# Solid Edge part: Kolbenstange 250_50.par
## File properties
Username: ahadarics
Dokumentum tartalom típus: 0
Author: ahadarics
Last saved by: ahadarics
Revision: 80
Sűrűség: 0,000 kg/m^3
Pontosság: 0,990
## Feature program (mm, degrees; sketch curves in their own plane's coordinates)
base feature "unnamed BaseFeature 1"
thread "unnamed Thread 1"
chamfer "Letörés_1"  SetBackValue2 = 20 deg
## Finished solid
Body 1: solid body, 19 faces, 27 edges, 11 vertices.
  Faces by surface: plane 8, cylinder 5, cone 3, torus 3
  Edges by curve: circle 15, line 7, curve on surface 3, ellipse 2
Bounding box of the edges (mm; curved faces can reach further): 250.000 x 250.000 x 379.000, from (-125, -125, -197) to (125, 125, 182).
Cylindrical faces by radius (mm): R19.4 x1, R21 x1, R24.5 x1, R25 x1, R125 x1
Conical faces (half-angle, radius in mm at the cone's reference point): 20 deg R21 x1, 30 deg R24.75 x1, 60 deg R20.2 x1
Toroidal faces (ring radius, tube radius in mm): R20.2 r0.8 x2, R22.5 r2 x1
Planar faces by outward normal: +x 1, +z 3, -x 1, -z 1, oblique 2
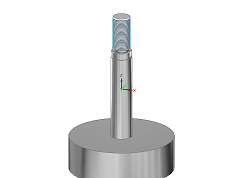
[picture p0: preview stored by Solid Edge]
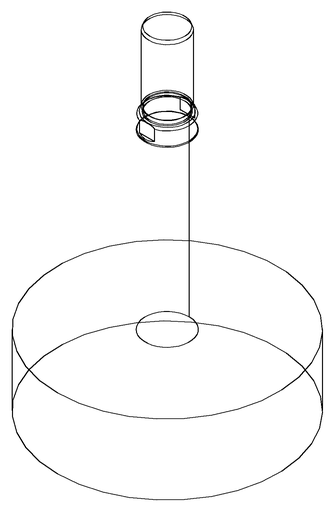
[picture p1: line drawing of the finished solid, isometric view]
